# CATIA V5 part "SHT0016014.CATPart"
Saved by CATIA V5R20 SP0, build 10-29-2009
Part number: SHT0016014-20241219
Source: Unknown
Bounding box of the stored display mesh (mm): x -544.085 to 25.758, y -866.5 to -591.5, z 0.9 to 106.4
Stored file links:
  F:\福田A6\1-数据\6-冻结数据\第九批\设变\宽车底部支架设变ECR0011068-20241213\SHT0016014-宽车主驾驶底部支架焊接总成\更改后数据-SHT0016014\SHT0016014-宽车主驾驶底部支架焊接总成\SHT0016014.CATPart
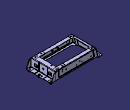
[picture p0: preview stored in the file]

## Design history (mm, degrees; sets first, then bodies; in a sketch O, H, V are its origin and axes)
Set1
  Point1 to Point4: stored without definition
Body1 "几何体" (main body)
Body2 "SHT0016151-支撑轴套"
  Solid1: solid without history
Body3 "SHT0016151-支撑轴套"
  Solid2: solid without history
Body4 "SHT0016151-支撑轴套"
Body5 "SHT0016014.1\\SHT0016145-宽车主驾驶前侧钣金"
  Solid3: solid without history
Body6 "SHT0016014.1\\SHT0016148-宽车主驾驶左侧钣金"
  Solid4: solid without history
Body7 "SHT0016014.1\\SHT0016148-宽车主驾驶左侧钣金"
  Solid5: solid without history
Body8 "SHT0016151-支撑轴套"
  Solid6: solid without history
Body9 "SHT0016014.1\\Q37108-焊接方螺母"
  Solid7: solid without history
Body10 "SHT0016014.1\\Q37108-焊接方螺母"
  Solid8: solid without history
Body11 "SHT0016014.1\\Q37108-焊接方螺母"
  Solid9: solid without history
Body12 "SHT0016014.1\\Q37108-焊接方螺母"
  Solid10: solid without history
Body13 "SHT0016014.1\\Q37108-焊接方螺母"
  Solid11: solid without history
Body14 "SHT0016014.1\\Q37108-焊接方螺母"
  Solid12: solid without history
Body15 "SHT0016014.1\\Q37106-焊接方螺母"
  Solid13: solid without history
Body16 "SHT0016014.1\\Q37110-焊接方螺母"
  Solid14: solid without history
Body17 "SHT0016014.1\\Q37110-焊接方螺母"
  Solid15: solid without history
Body18 "SHT0016014.1\\Q37106-焊接方螺母"
  Solid16: solid without history
Body19 "SHT0016014.1\\Q37106-焊接方螺母"
  Solid17: solid without history
Body20 "SHT0016014.1\\Q37106-焊接方螺母"
  Solid18: solid without history
Body21 "SHT0016014.1\\SHT0016146-宽车主驾驶后侧钣金"
  Solid19: solid without history
Body22 "Q37108-焊接方螺母"
  Solid20: solid without history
